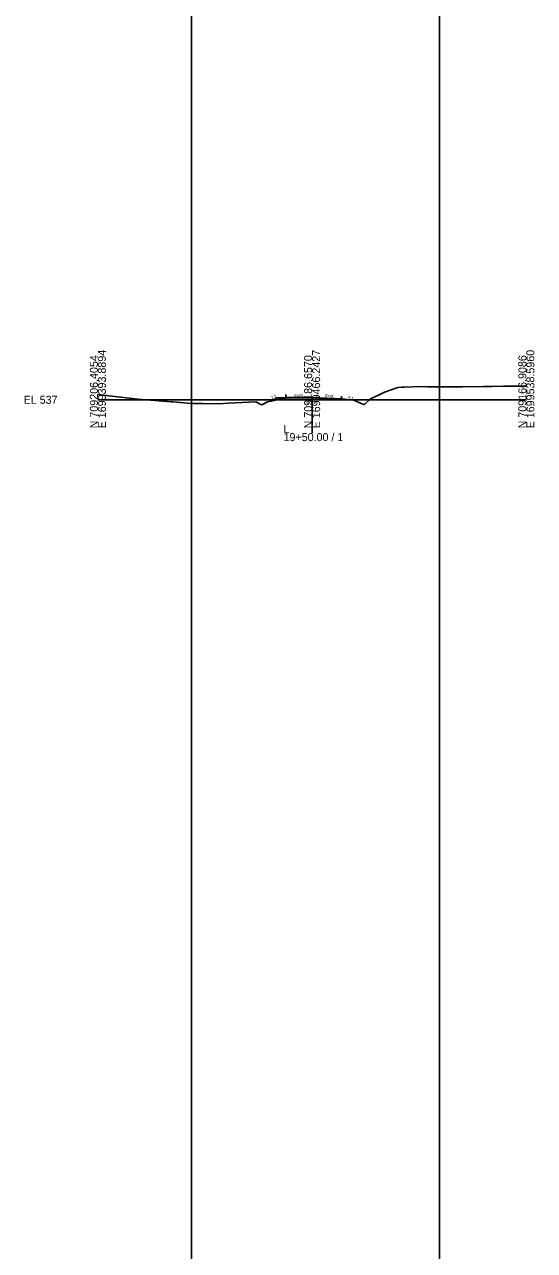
# Model space of a CAD drawing. Extents: x -63 to 1153, y -24 to 9522.
# Drawn here: x 974.3 to 1152.8, y 1702.4 to 2131.3 of the extents above; entities that cross this region are included whole.
import ezdxf

# ---------------------------------------------------------------- set-up
doc = ezdxf.new("R2010")
doc.units = 0
for name, color, linetype in [('Default', 7, 'Continuous'), ('Exist Cross Section Cell', 7, 'Continuous'), ('Exist XS Center Line Elevation Label', 7, 'Continuous'), ('Exist XS Ground Line', 7, 'Continuous'), ('Prop CMT DNC', 7, 'Continuous'), ('Prop CMT Pvmt Surface Overlay', 7, 'Continuous'), ('Prop CMT Slope Grass', 7, 'Continuous'), ('Prop XS Earthwork Shape', 7, 'Continuous'), ('Prop XS EOT Tick Mark', 7, 'Continuous'), ('Prop XS SE Text', 7, 'Continuous'), ('Prop XS Side Slope Text', 7, 'Continuous')]:
    doc.layers.add(name, color=color, linetype=linetype)

msp = doc.modelspace()

# ---------------------------------------------------------------- linework, layer by layer
at = {"layer": 'Exist Cross Section Cell'}
for p, q in [((1000, 2000), (1075, 2000)), ((1075, 2000), (1150, 2000)), ((1075, 2000), (1075, 1988.34))]:
    msp.add_line(p, q, dxfattribs=at)
at = {"layer": 'Exist XS Ground Line'}
msp.add_lwpolyline([(1000, 2001.81), (1013.93, 2000.27), (1017.03, 1999.95), (1025.67, 1999.33), (1026.18, 1999.26), (1032.63, 1998.75), (1036.79, 1998.68), (1042.23, 1998.59), (1045.63, 1998.81), (1055.29, 1999.31), (1056.58, 1998.59), (1057.38, 1998.23), (1058.3, 1998.68), (1059.41, 1999.3), (1061.75, 1999.77), (1063.85, 2000.33), (1065.57, 2000.55), (1071.7, 2000.63), (1075, 2000.67), (1075.28, 2000.67), (1081.48, 2000.35), (1084.72, 2000.14), (1089.37, 1999.9), (1089.61, 1999.87), (1091.95, 1998.87), (1093.08, 1998.37), (1093.21, 1998.32), (1093.41, 1998.49), (1095.41, 2000.34), (1098.48, 2001.72), (1100.38, 2002.61), (1104.62, 2004.16), (1105.05, 2004.33), (1106.27, 2004.42), (1107.39, 2004.42), (1113.05, 2004.63), (1115.45, 2004.56), (1119.89, 2004.53), (1127.69, 2004.57), (1134.95, 2004.59), (1137.92, 2004.64), (1141.95, 2004.71), (1150, 2004.82)], dxfattribs=at)
at = {"layer": 'Prop CMT DNC'}
msp.add_lwpolyline([(1032.78, 2560.22), (1119.63, 2560.22), (1119.63, 1449.3), (1032.78, 1449.3)], close=True, dxfattribs=at)
at = {"layer": 'Prop CMT Pvmt Surface Overlay'}
for points in [[(1075.28, 2000.78), (1065.79, 2000.8)], [(1075.28, 2000.78), (1085.28, 2000.3)]]:
    msp.add_lwpolyline(points, dxfattribs=at)
at = {"layer": 'Prop CMT Slope Grass'}
for p, q in [((1065.79, 2000.8), (1065.79, 2000.55)), ((1085.29, 2000.3), (1085.28, 2000.11))]:
    msp.add_line(p, q, dxfattribs=at)
for points in [[(1062.8, 2000.63), (1060.63, 1999.54)], [(1065.79, 2000.8), (1062.8, 2000.63)], [(1085.29, 2000.3), (1089.37, 1999.9)]]:
    msp.add_lwpolyline(points, dxfattribs=at)
at = {"layer": 'Prop XS Earthwork Shape'}
for points in [[(1061.75, 1999.77), (1063.85, 2000.33), (1065.57, 2000.55), (1065.79, 2000.55), (1065.79, 2000.8), (1062.8, 2000.63), (1060.63, 1999.54)], [(1085.28, 2000.11), (1089.37, 1999.9), (1085.29, 2000.3)]]:
    msp.add_lwpolyline(points, close=True, dxfattribs=at)
at = {"layer": 'Prop XS EOT Tick Mark'}
for points in [[(1065.8, 2000.8), (1065.8, 2001.8)], [(1085.28, 2000.3), (1085.28, 2001.3)]]:
    msp.add_lwpolyline(points, dxfattribs=at)

# ---------------------------------------------------------------- texts
at = {"layer": 'Default'}
msp.add_text('-', height=0.0001, dxfattribs=at).set_placement((1000, 2000))
msp.add_text('-', height=0.0001, dxfattribs=at).set_placement((1000, 2000))
at = {"layer": 'Exist Cross Section Cell'}
for s, p in [('E 1699393.8894', (1002.8, 1990)), ('E 1699466.2427', (1077.8, 1990)), ('E 1699538.5960', (1152.8, 1990)), ('N 709206.4054', (1000, 1990)), ('N 709186.6570', (1075, 1990)), ('N 709166.9086', (1150, 1990))]:
    msp.add_text(s, height=2.8, rotation=90, dxfattribs=at).set_placement(p)
for s, p in [('EL 537', (974, 1998.6)), ('L', (1065, 1988.34)), ('19+50.00 / 1', (1065, 1985.54))]:
    msp.add_text(s, height=2.8, dxfattribs=at).set_placement(p)
at = {"layer": 'Exist XS Center Line Elevation Label'}
msp.add_text('537.67', height=1, dxfattribs=at).set_placement((1072.85, 1998.56))
at = {"layer": 'Prop XS SE Text'}
for rotation, p in [(3.1485, (1068.78, 2001.04)), (356.5635, (1079.48, 2001.03))]:
    msp.add_text('Exist.', height=1, rotation=rotation, dxfattribs=at).set_placement(p)
at = {"layer": 'Prop XS Side Slope Text'}
for s, rotation, p in [('2:1', 26.5651, (1060.89, 2000.23)), ('4:1', 343.6849, (1087.47, 2000.48))]:
    msp.add_text(s, height=1, rotation=rotation, dxfattribs=at).set_placement(p)

doc.saveas('drawing.dxf')
